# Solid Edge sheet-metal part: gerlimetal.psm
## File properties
Author: priit
Template: Normal.psm
Last saved by: Anon
Revision: 5
Application: Solid Edge
Accuracy: 0,990
Material Thickness: 1,00 mm
Bend Radius: 1,00 mm
Relief Width: 1,00 mm
Relief Length: 0,00 mm
Neutral Factor: 0,330
Minimum Arc Length: 0,10 mm
Deviational Tolerance: 0,10 mm
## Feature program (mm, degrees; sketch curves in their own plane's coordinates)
base tab "unnamed BaseTab 1"
flange "Flange_1"
jog tab "JogTab_1"  OffsetDistance = 22.4375 mm
jog tab "JogTab_2"  OffsetDistance = 23.44 mm
dimple "Dimple_1"
bead "unnamed Bead 1"
bead "unnamed Bead 2"
bead "unnamed Bead 3"
dimple "Dimple_2"
dimple "Dimple_3"
louver "Louver_1"  LouverDepth = 3 mm; LouverHeight = 1.884 mm
pattern "unnamed Pattern 1" of "Louver_1"
pattern "unnamed Pattern 2"
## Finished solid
Body 1: solid body, 138 faces, 310 edges, 180 vertices.
  Faces by surface: plane 56, cylinder 36, torus 18, sphere 16, cone 12
  Edges by curve: line 156, circle 154
Bounding box of the edges (mm; curved faces can reach further): 41.860 x 50.000 x 11.000, from (-30.164, -19.4853, 0) to (11.696, 30.5147, 11).
Cylindrical faces by radius (mm): R0.25 x2, R1 x17, R1.25 x2, R1.5 x1, R2 x5, R2.3306 x4, R2.5 x1, R3.3306 x4
Conical faces (half-angle, radius in mm at the cone's reference point): 15 deg R0.3014 x3, 15 deg R0.6363 x3, 15 deg R1.2673 x3, 15 deg R1.6023 x3
Toroidal faces (ring radius, tube radius in mm): R0.25 r1 x2, R0.5 r1 x6, R1.25 r1 x2, R1.5 r1 x1, R1.6023 r1 x6, R2.5 r1 x1
Spherical faces by radius (mm): R2.3306 x8, R3.3306 x8
Planar faces by outward normal: +x 9, +y 8, +z 5, -x 9, -y 7, -z 6, oblique 12
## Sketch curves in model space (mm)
line (-30.164, -19.4853, 0) -> (11.696, -19.4853, 0)
line (11.696, -19.4853, 0) -> (11.696, 30.5147, 0)
line (11.696, 30.5147, 0) -> (-30.164, 30.5147, 0)
line (-30.164, 30.5147, 0) -> (-30.164, -19.4853, 0)
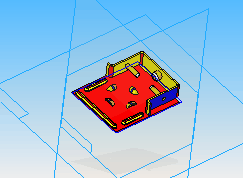
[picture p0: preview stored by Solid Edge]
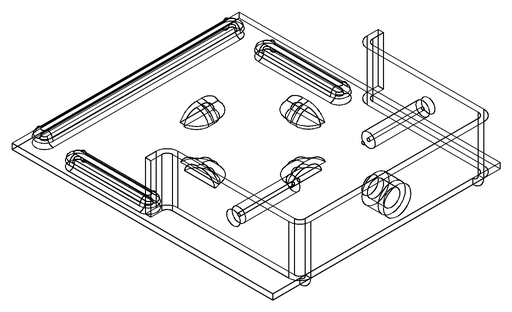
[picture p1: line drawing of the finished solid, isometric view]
